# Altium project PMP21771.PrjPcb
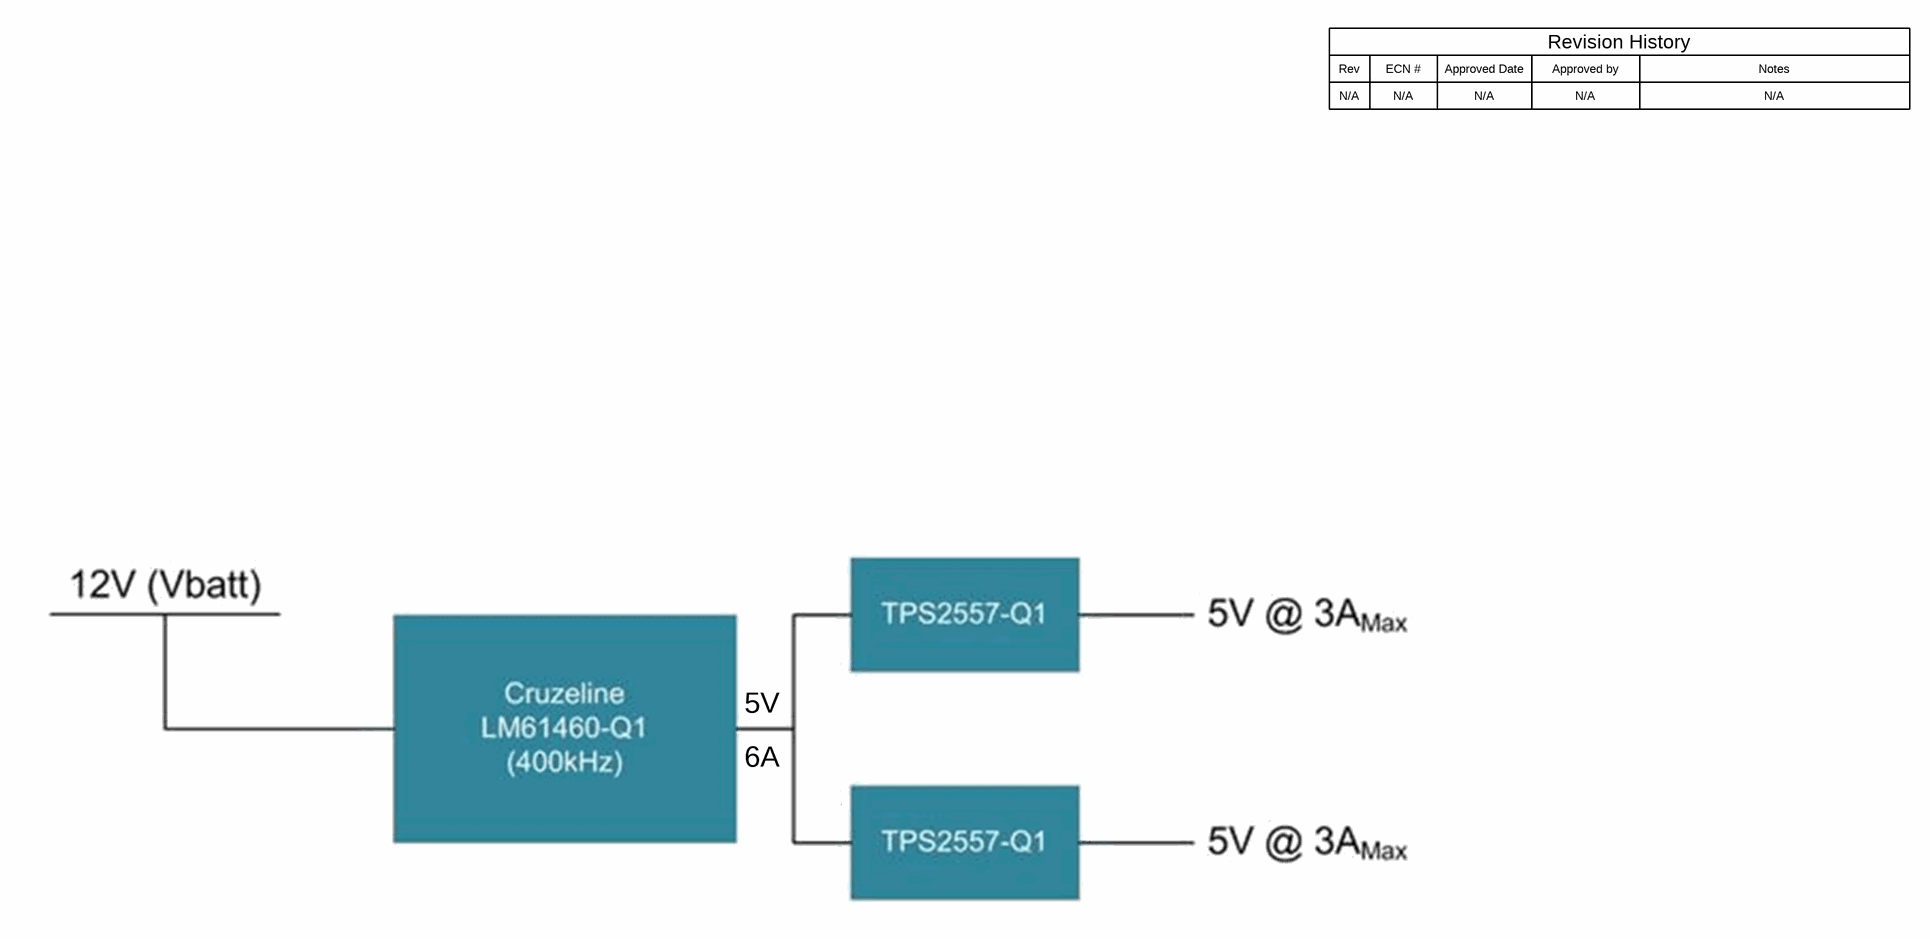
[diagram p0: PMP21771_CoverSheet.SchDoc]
TID: N/A; TechSupport: http://www.ti.com/support; SCH_Rev: E1; PRJ_Number: PMP21771; PRJ_Engineer: Sahana Krishnan; PRJ_Customer: Public Release; PCB_Rev: E1; PCB_Layout: Sahana Krishnan; CopyrightYear: 2018
3 sheets, 73 parts. Net scope: global (net labels, ports and power ports of the same name join across sheets).
Board file: PMP21771.PcbDoc
Sheets:
  PMP21771_CoverSheet.SchDoc
  PMP21771_Main.SchDoc
  PMP21771_Hardware.SchDoc

## Sheet PMP21771_CoverSheet.SchDoc
size 431 x 279 mm; Date: Not shown in title block; ApprovedBy: Not shown in title block; CheckedBy: Not shown in title block; Author: Not shown in title block; CompanyName: Not shown in title block; Engineer: Not shown in title block; Organization: Not shown in title block; Address1: Not shown in title block; Address2: Not shown in title block; Address3: Not shown in title block; Address4: Not shown in title block; DocumentNumber: 1; Revision: Use project parameter SCH_Rev; SheetNumber: 1; SheetTotal: 3; PageSetup: Record=PageOptions¦CenterHorizontal=True¦CenterVertical=True¦PrintScale=1.00¦XCorrection=1.00¦YCorrection=1.00¦PrintKind=0¦BorderSize=5000000¦LeftOffset=0¦BottomOffset=0¦Orientation=2¦PaperLength=1000¦PaperWidth=1000¦Scale=100¦PaperSource=15¦PrintQuality=600¦MediaType=1¦DitherType=10¦PaperKind=Letter¦PrintScaleMode=1

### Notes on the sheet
- Rev
- N/A
- ECN #
- Approved Date
- Approved by
- Revision History
- Notes
- 5V
- 6A

## Sheet PMP21771_Main.SchDoc
size 431 x 279 mm; Date: Not shown in title block; ApprovedBy: Not shown in title block; CheckedBy: Not shown in title block; Author: Not shown in title block; CompanyName: Not shown in title block; Engineer: Not shown in title block; Organization: Not shown in title block; Address1: Not shown in title block; Address2: Not shown in title block; Address3: Not shown in title block; Address4: Not shown in title block; DocumentNumber: 2; Revision: Use project parameter SCH_Rev; SheetNumber: 2; SheetTotal: 3; PageSetup: Record=PageOptions¦CenterHorizontal=True¦CenterVertical=True¦PrintScale=1.00¦XCorrection=1.00¦YCorrection=1.00¦PrintKind=0¦BorderSize=5000000¦LeftOffset=0¦BottomOffset=0¦Orientation=2¦PaperLength=1000¦PaperWidth=1000¦Scale=100¦PaperSource=15¦PrintQuality=600¦MediaType=1¦DitherType=10¦PaperKind=Letter¦PrintScaleMode=1
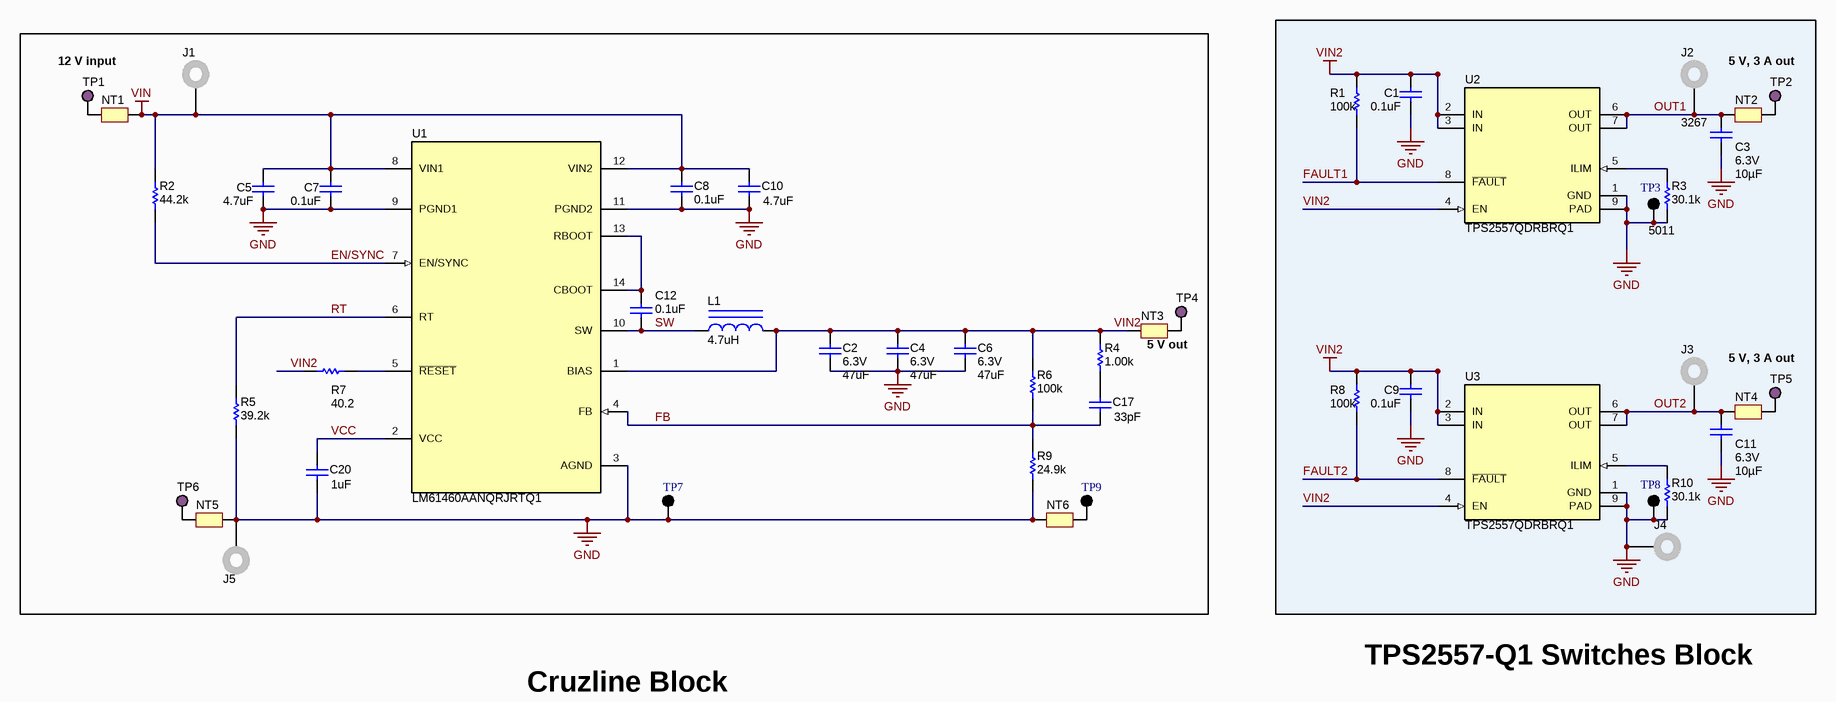
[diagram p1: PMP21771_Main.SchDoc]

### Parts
C1  ValueDisplayed: 0.1uF  [0402]  (hidden comment: C0402C104K4RACAUTO)
C2  VDC_V: 6.3V  ValueDisplayed: 47uF  [1210_270]  (hidden comment: GCM32ER70J476KE19L)
C3  VDC_V: 6.3V  ValueDisplayed: 10µF  [0805_HV]  (hidden comment: JMJ212CB7106KGHT)
C4  VDC_V: 6.3V  ValueDisplayed: 47uF  [1210_270]  (hidden comment: GCM32ER70J476KE19L)
C5  ValueDisplayed: 4.7uF  [1210_280]  (hidden comment: CGA6P3X7R1H475K250AB)
C6  VDC_V: 6.3V  ValueDisplayed: 47uF  [1210_270]  (hidden comment: GCM32ER70J476KE19L)
C7  ValueDisplayed: 0.1uF  [0402]  (hidden comment: CGA2B3X7R1H104K050BB)
C8  ValueDisplayed: 0.1uF  [0402]  (hidden comment: CGA2B3X7R1H104K050BB)
C9  ValueDisplayed: 0.1uF  [0402]  (hidden comment: C0402C104K4RACAUTO)
C10  ValueDisplayed: 4.7uF  [1210_280]  (hidden comment: CGA6P3X7R1H475K250AB)
C11  VDC_V: 6.3V  ValueDisplayed: 10µF  [0805_HV]  (hidden comment: JMJ212CB7106KGHT)
C12  ValueDisplayed: 0.1uF  [0402]  (hidden comment: C0402C104K4RACAUTO)
C17  ValueDisplayed: 33pF  [0402]  (hidden comment: C0402C330J5GACAUTO)
C20  ValueDisplayed: 1uF  [0603]  (hidden comment: GCM188R71C105KA64D)
J1  3267  [Pomona_3267]  (value not drawn)
J2  3267  [Pomona_3267]
J3  3267  [Pomona_3267]  (value not drawn)
J4  3267  [Pomona_3267]  (value not drawn)
J5  3267  [Pomona_3267]  (value not drawn)
L1  ValueDisplayed: 4.7uH  [XAL6060]  (hidden comment: XAL6060-472MEB)
NT1  Net-Tie  [Net-Tie_10mil]  (value not drawn)  (net tie, no BOM)
NT2  Net-Tie  [Net-Tie_10mil]  (value not drawn)  (net tie, no BOM)
NT3  Net-Tie  [Net-Tie_10mil]  (value not drawn)  (net tie, no BOM)
NT4  Net-Tie  [Net-Tie_10mil]  (value not drawn)  (net tie, no BOM)
NT5  Net-Tie  [Net-Tie_10mil]  (value not drawn)  (net tie, no BOM)
NT6  Net-Tie  [Net-Tie_10mil]  (value not drawn)  (net tie, no BOM)
R1  ValueDisplayed: 100k  [0402]  (hidden comment: ERJ-2RKF1003X)
R2  ValueDisplayed: 44.2k  [0402]  (hidden comment: CRCW040244K2FKED)
R3  ValueDisplayed: 30.1k  [0402]  (hidden comment: CRCW040230K1FKED)
R4  ValueDisplayed: 1.00k  [0603]  (hidden comment: CRCW06031K00FKEA)
R5  ValueDisplayed: 39.2k  [0402]  (hidden comment: CRCW040239K2FKED)
R6  ValueDisplayed: 100k  [0402]  (hidden comment: RMCF0402FT100K)
R7  ValueDisplayed: 40.2  [0402]  (hidden comment: CRCW040240R2FKED)
R8  ValueDisplayed: 100k  [0402]  (hidden comment: ERJ-2RKF1003X)
R9  ValueDisplayed: 24.9k  [0402]  (hidden comment: CRCW040224K9FKED)
R10  ValueDisplayed: 30.1k  [0402]  (hidden comment: CRCW040230K1FKED)
TP1  5129  [Keystone5129]  (value not drawn)
TP2  5129  [Keystone5129]  (value not drawn)
TP3  5011  [Keystone5011]
TP4  5129  [Keystone5129]  (value not drawn)
TP5  5129  [Keystone5129]  (value not drawn)
TP6  5129  [Keystone5129]  (value not drawn)
TP7  5011  [Keystone5011]  (value not drawn)
TP8  5011  [Keystone5011]  (value not drawn)
TP9  5011  [Keystone5011]  (value not drawn)
U1  LM61460AANQRJRTQ1  [RJR0014A]
U2  TPS2557QDRBRQ1  [DRB0008B]
U3  TPS2557QDRBRQ1  [DRB0008B]

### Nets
GND: C1.2 C2.2 C3.2 C4.2 C5.2 C6.2 C7.2 C8.2 C9.2 C10.2 C11.2 C20.2 J4.1 J5.1 NT5.2 NT6.1 R3.1 R5.1 R9.1 R10.1 TP3.1 TP7.1 TP8.1 U1.3(AGND) U1.9(PGND1) U1.11(PGND2) U2.1(GND) U2.9(PAD) U3.1(GND) U3.9(PAD)
VIN: C5.1 C7.1 C8.1 C10.1 J1.1 NT1.2 R2.2 U1.8(VIN1) U1.12(VIN2)
VIN2: C1.1 C2.1 C4.1 C6.1 C9.1 L1.2 NT3.1 R1.2 R4.2 R6.2 R7.2 R8.2 U1.1(BIAS) U2.2(IN) U2.3(IN) U2.4(EN) U3.2(IN) U3.3(IN) U3.4(EN)
EN/SYNC: R2.1 U1.7(EN/SYNC)
FAULT1: R1.1 U2.8(~{FAULT})
FAULT2: R8.1 U3.8(~{FAULT})
FB: C17.2 R6.1 R9.2 U1.4(FB)
OUT1: C3.1 J2.1 NT2.1 U2.6(OUT) U2.7(OUT)
OUT2: C11.1 J3.1 NT4.1 U3.6(OUT) U3.7(OUT)
RT: R5.2 U1.6(RT)
SW: C12.2 L1.1 U1.10(SW)
VCC: C20.1 U1.2(VCC)
NetC12_1: C12.1 U1.13(RBOOT) U1.14(CBOOT)
NetC17_1: C17.1 R4.1
NetNT1_1: NT1.1 TP1.1
NetNT2_2: NT2.2 TP2.1
NetNT3_2: NT3.2 TP4.1
NetNT4_2: NT4.2 TP5.1
NetNT5_1: NT5.1 TP6.1
NetNT6_2: NT6.2 TP9.1
NetR3_2: R3.2 U2.5(ILIM)
NetR7_1: R7.1 U1.5(~{RESET})
NetR10_2: R10.2 U3.5(ILIM)

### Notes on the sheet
- 12 V input
- 5 V, 3 A out
- (near NT3) 5 V out
- TPS2557-Q1 Switches Block
- Cruzline Block

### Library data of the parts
C1 C9 = CMP-0006237-2: CAP, CERM, 0.1 uF, 16 V, +/- 10%, X7R, AEC-Q200 Grade 1, 0402; Manufacturer: Kemet; TaMin_C: -55°C; Polarized: N; SizeAreaWB_mm2: 3; Value1: Unknown; U/M: EA; Value: 0.1uF; TaMax_C: 125°C; SizeZ_mm: 0.6; SizeX_mm: 1; SizeY_mm: 0.5; Value2: 16V; AEC Qualified: Y; Cap_F: 100nF; AEC Category: Q200
C2 C4 C6 = CMP-0009172-1: CAP, CERM, 47 uF, 6.3 V, +/- 10%, X7R, AEC-Q200 Grade 1, 1210; Manufacturer: MuRata; TaMin_C: -55°C; Polarized: N; SizeAreaWB_mm2: 14.7; Value1: Unknown; U/M: EA; Value: 47uF; TaMax_C: 125°C; SizeZ_mm: 2.7; SizeX_mm: 3.2; SizeY_mm: 2.5; Cap_Case: 1210; SizeArea_mm2: 8; AEC Qualified: Y; Cap_F: 47µF; AEC Grade: 1; AEC Category: Q200
C3 C11 = CMP-0081188-1: CAP, CERM, 10 µF, 6.3 V,+/- 10%, X7R, AEC-Q200 Grade 1, 0805; Manufacturer: Taiyo Yuden; TaMin_C: -55°C; Polarized: N; SizeAreaWB_mm2: 6.75; U/M: EA; Value: 10uF; TaMax_C: 125°C; SizeZ_mm: 1.45; SizeX_mm: 2; SizeY_mm: 1.25; Cap_Case: 0805; SizeArea_mm2: 2.5; AEC Qualified: Y; AEC Grade: 1; AEC Category: Q200
C5 C10 = CMP-0009162-1: CAP, CERM, 4.7 uF, 50 V, +/- 10%, X7R, AEC-Q200 Grade 1, 1210; Manufacturer: TDK; TaMin_C: -55°C; ESR_ohm: 3.166m; Polarized: N; SizeAreaWB_mm2: 14.7; Value1: 0.003166 ohm; U/M: EA; Value: 4.7uF; TaMax_C: 125°C; SizeZ_mm: 2.8; SizeX_mm: 3.2; SizeY_mm: 2.5; Value2: 50V; SizeArea_mm2: 8; AEC Qualified: Y; Cap_F: 4.7µF; IRMS_A: 4.13311A; AEC Grade: 1; AEC Category: Q200
C7 = CMP-0006325-1: CAP, CERM, 0.1 uF, 50 V, +/- 10%, X7R, AEC-Q200 Grade 1, 0402; Manufacturer: TDK; TaMin_C: -55°C; ESR_ohm: 0.039064; Polarized: N; SizeAreaWB_mm2: 3; Value1: 0.039064 ohm; U/M: EA; Value: 0.1uF; TaMax_C: 125°C; SizeZ_mm: 0.6; SizeX_mm: 1; SizeY_mm: 0.5; Value2: 50V; AEC Qualified: Y; Cap_F: 100nF; IRMS_A: 814.669mA; AEC Category: Q200
C8 = CMP-0006325-2: CAP, CERM, 0.1 uF, 50 V, +/- 10%, X7R, AEC-Q200 Grade 1, 0402; Manufacturer: TDK; TaMin_C: -55°C; ESR_ohm: 0.039064; Polarized: N; SizeAreaWB_mm2: 3; Value1: 0.039064 ohm; U/M: EA; Value: 0.1uF; TaMax_C: 125°C; SizeZ_mm: 0.6; SizeX_mm: 1; SizeY_mm: 0.5; Value2: 50V; AEC Qualified: Y; Cap_F: 100nF; IRMS_A: 814.669mA; AEC Category: Q200
C12 = CMP-0006237-1: CAP, CERM, 0.1 uF, 16 V, +/- 10%, X7R, AEC-Q200 Grade 1, 0402; Manufacturer: Kemet; TaMin_C: -55°C; Polarized: N; SizeAreaWB_mm2: 3; Value1: Unknown; U/M: EA; Value: 0.1uF; TaMax_C: 125°C; SizeZ_mm: 0.6; SizeX_mm: 1; SizeY_mm: 0.5; Value2: 16V; AEC Qualified: Y; Cap_F: 100nF; AEC Category: Q200
C17 = CMP-0079151-1: CAP, CERM, 33 pF, 50 V,+/- 5%, C0G, AEC-Q200 Grade 1, 0402; Manufacturer: Kemet; SizeAreaWB_mm2: 3; SizeArea_mm2: 0.5; AEC Qualified: Y; AEC Category: Q200; Value: 33pF; TaMax_C: 125°C; SizeZ_mm: 0.6; AEC Grade: 1; Polarized: N; TaMin_C: -55°C; Value2: 50V; U/M: EA
C20 = CMP-0007136-1: CAP, CERM, 1 uF, 16 V, +/- 10%, X7R, AEC-Q200 Grade 1, 0603; Manufacturer: MuRata; TaMin_C: -55°C; Polarized: N; SizeAreaWB_mm2: 4.68; Value1: Unknown; U/M: EA; Value: 1uF; TaMax_C: 125°C; SizeZ_mm: 1; SizeX_mm: 1.6; SizeY_mm: 0.8; Value2: 16V; SizeArea_mm2: 1.28; AEC Qualified: Y; Cap_F: 1µF; AEC Category: Q200
J1-J5 = CMP-0055388-2: Standard Banana Jack, Uninsulated; Manufacturer: Pomona Electronics; CT: TRUE; Green_REACh: Incomplete; CNHeader: FALSE; Green_Lifecycle: Not Set
L1 = CMP-0061020-1: Inductor, Shielded, Composite, 4.7 uH, 10.5 A, 0.015 ohm, SMD; Manufacturer: Coilcraft; Isat: 10.5A @ 30% inductance drop; Irms: 12.3A @ 40C rise; Green_Lifecycle: Not Set; SizeAreaWB_mm2: 71.5616; DCR_ohm: 0.015; Green_REACh: Incomplete; Value: 4.7uH; Imax_A: 10.5A; SizeZ_mm: 6.1; SizeX_mm: 6.36; SizeY_mm: 6.56; SizeArea_mm2: 41.7216; Ind_H: 4.7µH; AEC Category: Q200
NT1-NT6 = CMP-0078142-1: Single point connection between nets.
R1 R8 = CMP-0026659-1: RES, 100 k, 1%, 0.1 W, 0402; Manufacturer: Panasonic; Power_W: 100mW; TempCo: 100 ppm/C; U/M: EA; Value: 100k; EIA_Code: E96; SizeX_mm: 1; SizeY_mm: 0.5; SizeZ_mm: 0.6; Value2: 0.1W; VDC_V: 50V; AEC Category: Q200
R2 = CMP-0026383-2: RES, 44.2 k, 1%, 0.063 W, AEC-Q200 Grade 0, 0402; Manufacturer: Vishay-Dale; Power_W: 63mW; TempCo: 100 ppm/C; Value_Code: 44k2; Value: 44.2k; EIA_Code: E96; SizeX_mm: 1; SizeY_mm: 0.5; SizeZ_mm: 0.6; Value2: 0.063W; AEC Qualified: Y; VDC_V: 50V; AEC Category: Q200; AEC Grade: 0
R3 R10 = CMP-0026284-2: RES, 30.1 k, 1%, 0.063 W, AEC-Q200 Grade 0, 0402; Manufacturer: Vishay-Dale; Power_W: 63mW; TempCo: 100 ppm/C; Value_Code: 30k1; Value: 30.1k; EIA_Code: E96; SizeX_mm: 1; SizeY_mm: 0.5; SizeZ_mm: 0.6; Value2: 0.063W; AEC Qualified: Y; VDC_V: 50V; AEC Category: Q200; AEC Grade: 0
R4 = CMP-0022109-5: RES, 1.00 k, 1%, 0.1 W, AEC-Q200 Grade 0, 0603; Manufacturer: Vishay-Dale; Power_W: 100mW; TempCo: 100 ppm/C; Value_Code: 1k00; Value: 1.00k; EIA_Code: E96; Res_ohm: 1k; SizeX_mm: 1.6; SizeY_mm: 0.8; SizeZ_mm: 1; Value2: 0.1W; SizeArea_mm2: 1.28; AEC Qualified: Y; VDC_V: 75V; AEC Category: Q200; AEC Grade: 0
R5 = CMP-0026327-2: RES, 39.2 k, 1%, 0.063 W, AEC-Q200 Grade 0, 0402; Manufacturer: Vishay-Dale; Power_W: 63mW; TempCo: 100 ppm/C; Value_Code: 39k2; Value: 39.2k; EIA_Code: E96; SizeX_mm: 1; SizeY_mm: 0.5; SizeZ_mm: 0.6; Value2: 0.063W; AEC Qualified: Y; VDC_V: 50V; AEC Category: Q200; AEC Grade: 0
R6 = CMP-0026753-1: RES, 100 k, 1%, 0.063 W, AEC-Q200 Grade 0, 0402; Manufacturer: Stackpole Electronics Inc; Power_W: 63mW; TempCo: 100 ppm/C; U/M: EA; Value: 100k; EIA_Code: E96; SizeX_mm: 1; SizeY_mm: 0.5; SizeZ_mm: 0.6; Value2: 0.063W; AEC Qualified: Y; VDC_V: 50V; AEC Grade: 0; AEC Category: Q200
R7 = CMP-0026368-2: RES, 40.2, 1%, 0.063 W, AEC-Q200 Grade 0, 0402; Manufacturer: Vishay-Dale; Power_W: 63mW; TempCo: 100 ppm/C; Value_Code: 40R2; Value: 40.2; EIA_Code: E96; SizeX_mm: 1; SizeY_mm: 0.5; SizeZ_mm: 0.6; Value2: 0.063W; AEC Qualified: Y; VDC_V: 50V; AEC Category: Q200; AEC Grade: 0
R9 = CMP-0026196-2: RES, 24.9 k, 1%, 0.063 W, AEC-Q200 Grade 0, 0402; Manufacturer: Vishay-Dale; Power_W: 63mW; TempCo: 100 ppm/C; Value_Code: 24k9; Value: 24.9k; EIA_Code: E96; SizeX_mm: 1; SizeY_mm: 0.5; SizeZ_mm: 0.6; Value2: 0.063W; AEC Qualified: Y; VDC_V: 50V; AEC Category: Q200; AEC Grade: 0
TP1 TP2 TP4-TP6 = CMP-0055160-1: Test Point, Multipurpose, Purple, TH; Manufacturer: Keystone; CNHeader: FALSE; ContactFinish: Silver; CT: TRUE
TP3 TP7-TP9 = CMP-0055148-1: Test Point, Multipurpose, Black, TH; Manufacturer: Keystone; CNHeader: FALSE; Green_Lifecycle: Active; Green_REACh: Passed; ContactFinish: Silver; CT: TRUE
U1 = CMP-0079820-1: Automotive 6-A Low Noise Synchronous Buck Regulators, RJR0014A (VQFN-HR-14); Alternate Manufacturer: Texas Instruments; SizeAreaWB_mm2: 22.5; SizeZ_mm: 1; SizeX_mm: 4; SizeY_mm: 3.5; SizeArea_mm2: 14; CompType: IC; AEC Qualified: Y; AEC Category: Q200
U2 U3 = CMP-0074282-3: PRECISION ADJUSTABLE CURRENT-LIMITED POWER-DISTRIBUTION SWITCHES, DRB0008B (VSON-8); Alternate PartNumber: TPS2557QDRBTQ1; Manufacturer: Texas Instruments; SizeZ_mm: 1.0; SizeX_mm: 3.0; SizeArea_mm2: 9.0; CompType: IC; SizeAreaWB_mm2: 16.0; AEC Category: Q200; AEC Qualified: Y

## Sheet PMP21771_Hardware.SchDoc
size 431 x 279 mm; Date: Not shown in title block; ApprovedBy: Not shown in title block; CheckedBy: Not shown in title block; Author: Not shown in title block; CompanyName: Not shown in title block; Engineer: Not shown in title block; Organization: Not shown in title block; Address1: Not shown in title block; Address2: Not shown in title block; Address3: Not shown in title block; Address4: Not shown in title block; DocumentNumber: 3; Revision: Use project parameter SCH_Rev; SheetNumber: 3; SheetTotal: 3; PageSetup: Record=PageOptions¦CenterHorizontal=True¦CenterVertical=True¦PrintScale=1.00¦XCorrection=1.00¦YCorrection=1.00¦PrintKind=0¦BorderSize=5000000¦LeftOffset=0¦BottomOffset=0¦Orientation=2¦PaperLength=1000¦PaperWidth=1000¦Scale=100¦PaperSource=15¦PrintQuality=600¦MediaType=1¦DitherType=10¦PaperKind=Letter¦PrintScaleMode=1
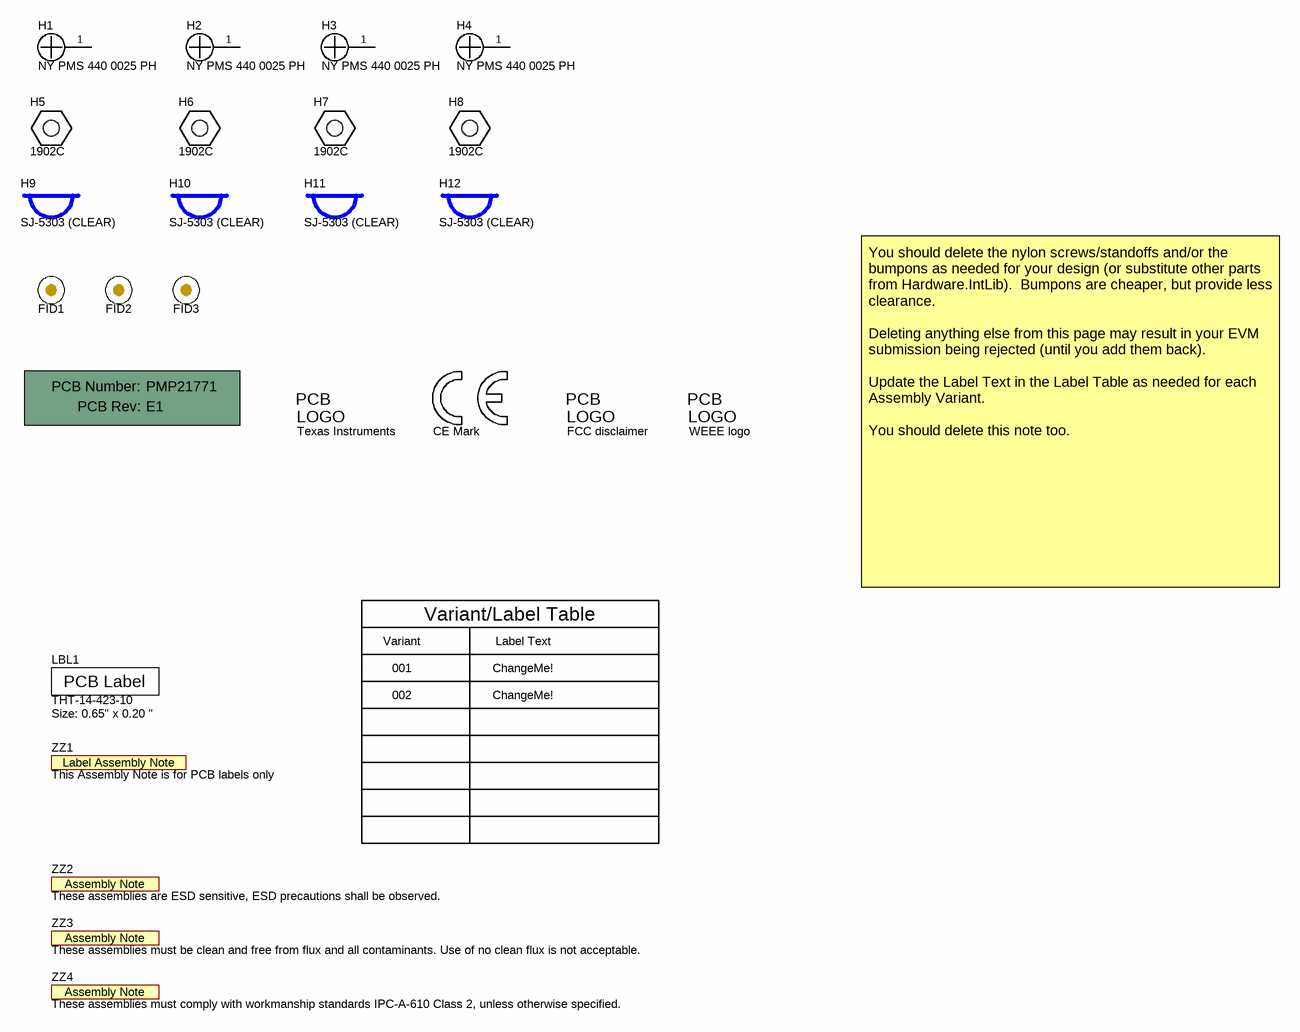
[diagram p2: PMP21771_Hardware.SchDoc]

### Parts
!PCB  Printed Circuit Board  (value not drawn)  (mechanical)
FID1  Fiducial  [Fiducial10-20]  (value not drawn)
FID2  Fiducial  [Fiducial10-20]  (value not drawn)
FID3  Fiducial  [Fiducial10-20]  (value not drawn)
H1  NY PMS 440 0025 PH  [NY PMS 440 0025 PH]
H2  NY PMS 440 0025 PH  [NY PMS 440 0025 PH]
H3  NY PMS 440 0025 PH  [NY PMS 440 0025 PH]
H4  NY PMS 440 0025 PH  [NY PMS 440 0025 PH]
H5  1902C  [Keystone_1902C]
H6  1902C  [Keystone_1902C]
H7  1902C  [Keystone_1902C]
H8  1902C  [Keystone_1902C]
H9  SJ-5303 (CLEAR)  [Bumpon_SJ5003Transparent]
H10  SJ-5303 (CLEAR)  [Bumpon_SJ5003Transparent]
H11  SJ-5303 (CLEAR)  [Bumpon_SJ5003Transparent]
H12  SJ-5303 (CLEAR)  [Bumpon_SJ5003Transparent]
LBL1  THT-14-423-10  Note: Size: 0.65" x 0.20 "  [Label_650x200]
Logo1  Texas Instruments  [TI_Stacked_Overlay_Small]  (no BOM)
Logo2  CE Mark  [CE_Mark_5mm]  (no BOM)
Logo3  FCC disclaimer  [FCC_disclaimer]  (no BOM)
Logo4  WEEE logo  [WEEE_Minimum]  (no BOM)
ZZ1  This Assembly Note is for PCB labels only  [AssemblyNoteLabel]  (no BOM)
ZZ2  These assemblies are ESD sensitive, ESD precautions shall be observed.  [AssemblyNote]  (no BOM)
ZZ3  These assemblies must be clean and free from flux and all contaminants. Use of no clean flux is not acceptable.  [AssemblyNote]  (no BOM)
ZZ4  These assemblies must comply with workmanship standards IPC-A-610 Class 2, unless otherwise specified.  [AssemblyNote]  (no BOM)

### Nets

Not connected (* = marked no-connect by the designer): H1 1; H2 1; H3 1; H4 1

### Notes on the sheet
- Variant
- Variant/Label Table
- Label Text
- You should delete the nylon screws/standoffs and/or the bumpons as needed for your design (or substitute other parts from Hardware.IntLib).  Bumpons are cheaper, but provide less clearance.
  Deleting anything else from this page may result in your EVM submission being rejected (until you add them back).
  Update the Label Text in the Label Table as needed for each Assembly Variant.
  You should delete this note too.
- 001
- 002
- ChangeMe!

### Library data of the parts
!PCB = CMP-0003618-2: Manufacturer: Any; PartNumber: PMP21771
FID1-FID3 = CMP-0077181-1: Fiducial mark.  There is nothing to buy or mount.
H1-H4 = CMP-0003617-1: Machine Screw, Round, #4-40 x 1/4, Nylon, Philips panhead; Manufacturer: B&F Fastener Supply; CompType: Hardware
H5-H8 = CMP-0003610-1: Standoff, Hex, 0.5"L #4-40 Nylon; Manufacturer: Keystone; CompType: Hardware
H9-H12 = CMP-0003620-1: Bumpon, Hemisphere, 0.44 X 0.20, Clear; Manufacturer: 3M
LBL1 = CMP-0003625-1: Thermal Transfer Printable Labels, 0.650" W x 0.200" H - 10,000 per roll; Manufacturer: Brady; CompType: Label
Logo1 = CMP-0074838-1: Texas Instrument Corporate Signature; SymbolCreator: a0412235; Lib Reference: TI_Logo; Library Reference: Logo
Logo2 = CMP-0074844-1: SymbolCreator: a0412235
Logo3 = CMP-0074847-1: FCC_disclaimer; Library Reference: Logo
Logo4 = CMP-0074769-1
ZZ1 = CMP-0003616-3
ZZ2 = CMP-0077236-1
ZZ3 = CMP-0077237-1
ZZ4 = CMP-0077238-1

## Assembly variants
001: not fitted FID1 FID2 FID3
